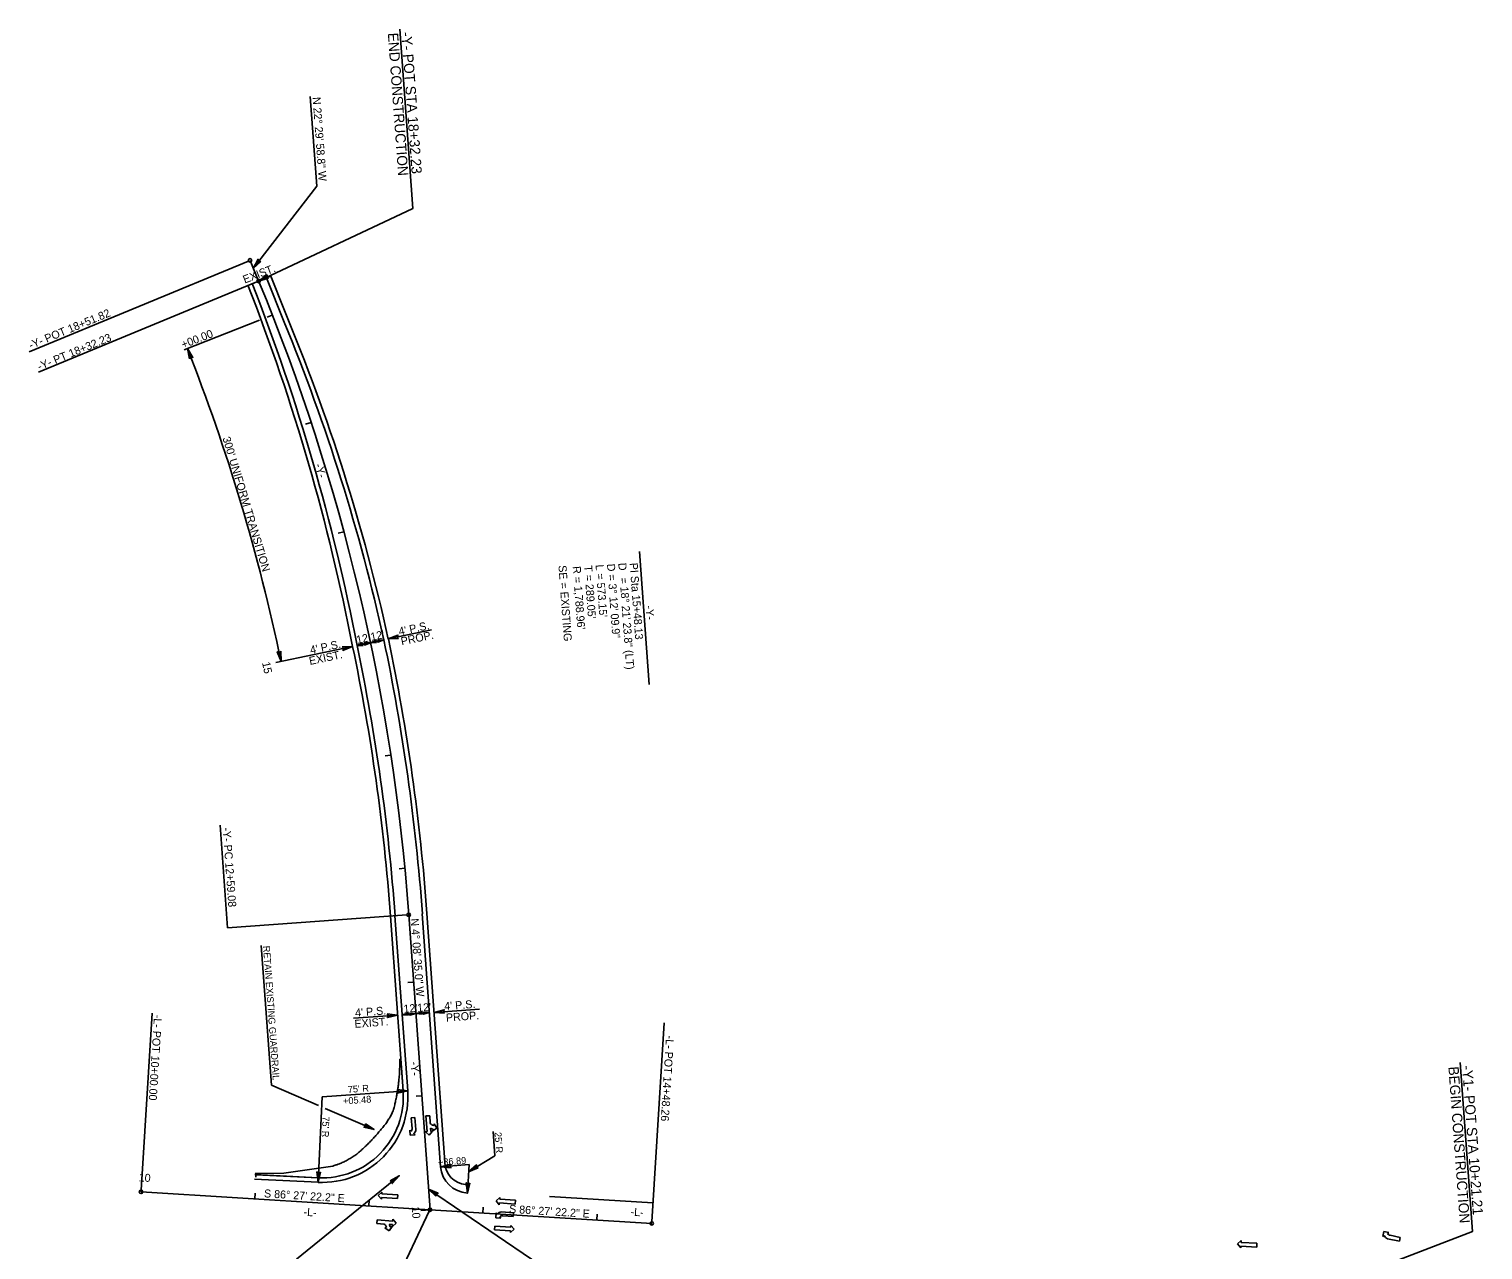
# Model space of a CAD drawing. Extents: x 2130900 to 2132500, y 642139 to 644213.
# Drawn here: x 2130900 to 2132174, y 643143 to 644213 of the extents above; entities that cross this region are included whole.
import ezdxf

# ---------------------------------------------------------------- set-up
doc = ezdxf.new("R2010")
doc.units = 0
for name, color, linetype in [('Prop Dimension', 7, 'Continuous'), ('Prop Dimension Text', 7, 'Continuous'), ('Prop DSN Text', 7, 'Continuous'), ('Prop EOT', 7, 'Continuous'), ('Prop Horizontal Alignment', 7, 'Continuous'), ('Prop Horizontal Alignment Curve and Spiral Data', 7, 'Continuous'), ('Prop Horizontal Alignment Direction Label', 7, 'Continuous'), ('Prop Horizontal Alignment Station Label', 7, 'Continuous'), ('Prop Horizontal Alignment Tick Label', 7, 'Continuous'), ('Prop Horizontal Alignment Tick Large', 7, 'Continuous'), ('Prop Horizontal Alignment Tick Small', 7, 'Continuous'), ('Prop Lane Lines', 7, 'Continuous'), ('Prop Paved Shoulder', 7, 'Continuous'), ('Prop Rem of Exist Asph Pvmt', 7, 'Continuous'), ('Prop Terminator CELL', 7, 'Continuous')]:
    doc.layers.add(name, color=color, linetype=linetype)

msp = doc.modelspace()

# ---------------------------------------------------------------- linework, layer by layer
at = {"layer": 'Prop Dimension'}
for p, q in [((2131102, 643957.9), (2131036, 643932)), ((2131199.2, 643675.3), (2131211, 643677.8)), ((2131214.9, 643678.6), (2131252.9, 643686.6)), ((2131116.5, 643657.9), (2131183.6, 643672)), ((2131187.5, 643672.8), (2131199.2, 643675.3)), ((2131184.4, 643346.3), (2131223.1, 643349.1)), ((2131227.1, 643349.4), (2131239, 643350.3)), ((2131239, 643350.3), (2131251, 643351.2)), ((2131255, 643351.4), (2131294.7, 643354.3)), ((2131231.9, 643282.8), (2131157.1, 643277.4))]:
    msp.add_line(p, q, dxfattribs=at)
msp.add_arc((2129448.5, 643307.7), 1709, 11.8592, 21.4674, dxfattribs=at)
at = {"layer": 'Prop Dimension Text'}
for p, q in [((2131103.7, 643410.1), (2131112.6, 643287.7)), ((2131112.6, 643287.7), (2131153.7, 643269.9)), ((2131159.7, 643267.2), (2131202.5, 643248.7)), ((2131399.3, 643095.3), (2131250.2, 643196.6))]:
    msp.add_line(p, q, dxfattribs=at)
for points in [[(2131224.9, 644213.1), (2131236.3, 644055.8), (2131101.3, 643992.3)], [(2132153.8, 643307.6), (2132164.7, 643159.4), (2132043.2, 643112.7)]]:
    msp.add_lwpolyline(points, dxfattribs=at)
at = {"layer": 'Prop DSN Text'}
for p, q in [((2131153.4, 643202.5), (2131157.1, 643277.4)), ((2131308.4, 643225.8), (2131306.9, 643247)), ((2131285.3, 643211.7), (2131308.4, 643225.8)), ((2131134.6, 643135.3), (2131224.5, 643208.3)), ((2131285.7, 643218), (2131260.8, 643216.2)), ((2131284.3, 643193), (2131285.7, 643218))]:
    msp.add_line(p, q, dxfattribs=at)
at = {"layer": 'Prop EOT'}
for p, q in [((2131101.3, 643992.3), (2131111.8, 643996.6)), ((2131123.7, 643956.1), (2131108.1, 643995.1)), ((2131095.7, 643989.9), (2131101.3, 643992.3)), ((2131231.9, 643282.8), (2131220.8, 643436)), ((2131260.8, 643216.2), (2131244.7, 643437.8)), ((2131097.7, 643205.3), (2131153.4, 643202.5))]:
    msp.add_line(p, q, dxfattribs=at)
for centre, radius, start, end in [((2129402.5, 643327.8), 1818.1, 10.9409, 21.3592), ((2129575, 643317.6), 1675.2, 12.4162, 22.4051), ((2129448.5, 643307.7), 1801, 4.1431, 11.8592), ((2129448.5, 643307.7), 1777, 4.1431, 11.8592), ((2131157.1, 643277.4), 75, 267.1687, 4.1431), ((2131285.7, 643218), 25, 184.1431, 266.6762)]:
    msp.add_arc(centre, radius, start, end, dxfattribs=at)
at = {"layer": 'Prop Horizontal Alignment'}
for p, q in [((2131101.3, 643992.3), (2131093.8, 644010.4)), ((2131251.5, 643178.5), (2131232.8, 643436.9)), ((2130998.3, 643194.2), (2131251.5, 643178.5)), ((2131251.5, 643178.5), (2131445.7, 643166.5))]:
    msp.add_line(p, q, dxfattribs=at)
msp.add_arc((2129448.5, 643307.7), 1789, 4.1431, 22.4997, dxfattribs=at)
at = {"layer": 'Prop Horizontal Alignment Curve and Spiral Data'}
msp.add_line((2131435.1, 643755.4), (2131443.5, 643638.7), dxfattribs=at)
at = {"layer": 'Prop Horizontal Alignment Direction Label'}
for p, q in [((2131152.3, 644075.3), (2131146.6, 644154.1)), ((2131096.5, 644003.3), (2131152.3, 644075.3))]:
    msp.add_line(p, q, dxfattribs=at)
at = {"layer": 'Prop Horizontal Alignment Station Label'}
for p, q in [((2131092.4, 644009.8), (2130900.2, 643930.2)), ((2131099.9, 643991.7), (2130908.5, 643912.4)), ((2131074.2, 643425.4), (2131067.7, 643515.4)), ((2131231.3, 643436.8), (2131074.2, 643425.4)), ((2130998.4, 643195.7), (2131008, 643350.8)), ((2131445.8, 643168), (2131456.6, 643342.2)), ((2131250.8, 643177.2), (2131211.1, 643093.2))]:
    msp.add_line(p, q, dxfattribs=at)
for centre in [(2131093.8, 644010.4), (2131101.3, 643992.3), (2131232.8, 643436.9), (2130998.3, 643194.2), (2131251.5, 643178.5), (2131251.5, 643178.5), (2131445.7, 643166.5)]:
    msp.add_circle(centre, 1.5, dxfattribs=at)
at = {"layer": 'Prop Horizontal Alignment Tick Large'}
for p, q in [((2131199.2, 643675.3), (2131191.4, 643673.7)), ((2130998.3, 643194.2), (2130998.8, 643202.2)), ((2131251.5, 643178.5), (2131243.5, 643177.9))]:
    msp.add_line(p, q, dxfattribs=at)
at = {"layer": 'Prop Horizontal Alignment Tick Small'}
for p, q in [((2131113.3, 643962.4), (2131108.7, 643960.5)), ((2131147.3, 643868.3), (2131142.5, 643866.8)), ((2131176, 643772.5), (2131171.1, 643771.2)), ((2131217, 643576.9), (2131212.1, 643576.2)), ((2131229.3, 643477.7), (2131224.4, 643477.2)), ((2131237, 643378), (2131232, 643377.6)), ((2131244.2, 643278.2), (2131239.3, 643277.9)), ((2131098.1, 643188), (2131098.4, 643193)), ((2131197.9, 643181.8), (2131198.2, 643186.8)), ((2131297.7, 643175.6), (2131298.1, 643180.6)), ((2131397.6, 643169.5), (2131397.9, 643174.5))]:
    msp.add_line(p, q, dxfattribs=at)
at = {"layer": 'Prop Lane Lines'}
msp.add_line((2131356.2, 643190.1), (2131446.8, 643184.4), dxfattribs=at)
at = {"layer": 'Prop Paved Shoulder'}
for p, q in [((2131123.9, 643966.5), (2131111.9, 643996.6)), ((2131227.9, 643282.6), (2131216.8, 643435.8)), ((2131264.8, 643216.5), (2131248.7, 643438.1)), ((2131097.9, 643209.3), (2131153.6, 643206.5))]:
    msp.add_line(p, q, dxfattribs=at)
for centre, radius, start, end in [((2129402.5, 643327.8), 1814.1, 10.9409, 21.3592), ((2129574.8, 643318.3), 1679.2, 12.3892, 22.706), ((2129448.5, 643307.7), 1805, 4.1431, 11.8598), ((2129448.5, 643307.7), 1773, 4.1431, 11.8592), ((2131157.1, 643277.4), 71, 267.1687, 4.1431), ((2131284.6, 643220.7), 20.3, 192.2078, 274.7409)]:
    msp.add_arc(centre, radius, start, end, dxfattribs=at)
at = {"layer": 'Prop Rem of Exist Asph Pvmt'}
for p, q in [((2131225.9, 643310.3), (2131225, 643310.3)), ((2131227.9, 643282.6), (2131225.9, 643310.3)), ((2131098.8, 643210.8), (2131099, 643207)), ((2131123.5, 643210.5), (2131098.8, 643210.2)), ((2131098.8, 643210.2), (2131098.9, 643209.2)), ((2131098.9, 643209.2), (2131153.6, 643206.5))]:
    msp.add_line(p, q, dxfattribs=at)
msp.add_lwpolyline([(2131166.2, 643216.7), (2131148, 643213.9), (2131123.5, 643210.5)], dxfattribs=at)
msp.add_arc((2131157.1, 643277.4), 71, 267.1687, 4.1431, dxfattribs=at)
msp.add_open_spline([(2131225, 643310.3), (2131225, 643304.8), (2131224.8, 643299.4), (2131224.4, 643293.9), (2131224, 643289.9), (2131223.5, 643286), (2131222.8, 643282), (2131222.2, 643278), (2131221.4, 643274), (2131220.5, 643270.1), (2131220.1, 643268.1), (2131219.4, 643266.2), (2131218.7, 643264.3), (2131218, 643262.5), (2131217.1, 643260.7), (2131216.1, 643259), (2131213.8, 643255.5), (2131211.5, 643252.2), (2131208.8, 643249.1), (2131206.1, 643245.9), (2131203.4, 643242.7), (2131200.5, 643239.7), (2131197.7, 643236.7), (2131194.8, 643233.9), (2131191.8, 643231.1), (2131188.9, 643228.5), (2131185.8, 643226.1), (2131182.4, 643224), (2131179, 643221.9), (2131175.5, 643220.1), (2131171.8, 643218.7), (2131170, 643218), (2131168.1, 643217.4), (2131166.2, 643216.7)], degree=3, dxfattribs=at)
at = {"layer": 'Prop Terminator CELL'}
for p, q in [((2131238.2, 643259.3), (2131234.9, 643259)), ((2131239.1, 643248.8), (2131238.2, 643259.3)), ((2131251.2, 643260.9), (2131247.9, 643260.7)), ((2131247.9, 643260.7), (2131248.9, 643246.9)), ((2131251.7, 643254.5), (2131251.2, 643260.9)), ((2131234.8, 643247.3), (2131233.7, 643248.2)), ((2131233.7, 643248.2), (2131234.1, 643243.8)), ((2131234.1, 643243.8), (2131238.5, 643244.1)), ((2131234.8, 643247.3), (2131234.8, 643247.3)), ((2131239.1, 643248.7), (2131239.1, 643248.8)), ((2131248.9, 643246.9), (2131247.4, 643246.8)), ((2131247.4, 643246.8), (2131250.7, 643243.9)), ((2131250.7, 643243.9), (2131253.7, 643247.2)), ((2131252.2, 643247.1), (2131252, 643250)), ((2131253.7, 643247.2), (2131252.2, 643247.1)), ((2131253.8, 643247.5), (2131257.5, 643250)), ((2131254.1, 643249), (2131253.8, 643247.5)), ((2131255.1, 643253.7), (2131254.8, 643252.3)), ((2131257.5, 643250), (2131255.1, 643253.7)), ((2131206.1, 643191), (2131209.4, 643193.9)), ((2131209.4, 643193.9), (2131209.3, 643192.4)), ((2131209.1, 643187.7), (2131206.1, 643191)), ((2131223.1, 643188.3), (2131209.1, 643189.1)), ((2131209.1, 643189.1), (2131209.1, 643187.7)), ((2131209.3, 643192.4), (2131223.3, 643191.6)), ((2131223.3, 643191.6), (2131223.1, 643188.3)), ((2131309.3, 643186.2), (2131312.6, 643189.1)), ((2131312.2, 643182.9), (2131309.3, 643186.2)), ((2131312.3, 643184.4), (2131312.2, 643182.9)), ((2131326.2, 643183.5), (2131312.3, 643184.4)), ((2131312.6, 643189.1), (2131312.5, 643187.7)), ((2131312.5, 643187.7), (2131326.4, 643186.8)), ((2131326.4, 643186.8), (2131326.2, 643183.5)), ((2131204.8, 643166.4), (2131205.1, 643169.7)), ((2131205.1, 643169.7), (2131218.8, 643168.6)), ((2131218.8, 643168.6), (2131219, 643170.1)), ((2131219, 643170.1), (2131221.8, 643166.8)), ((2131309.5, 643175.9), (2131309.2, 643171.4)), ((2131309.2, 643171.4), (2131313.6, 643171.2)), ((2131310.6, 643174.6), (2131309.5, 643175.9)), ((2131313.6, 643171.2), (2131312.7, 643172.2)), ((2131324.6, 643175.9), (2131314.1, 643176.6)), ((2131315.2, 643173.2), (2131324.4, 643172.6)), ((2131324.4, 643172.6), (2131324.6, 643175.9)), ((2131211.3, 643165.9), (2131204.8, 643166.4)), ((2131212, 643162.5), (2131213.4, 643162.8)), ((2131215.7, 643160), (2131212, 643162.5)), ((2131218.2, 643163.7), (2131215.7, 643160)), ((2131218.6, 643165.4), (2131215.8, 643165.6)), ((2131216.7, 643163.4), (2131218.2, 643163.7)), ((2131221.8, 643166.8), (2131218.5, 643163.9)), ((2131218.5, 643163.9), (2131218.6, 643165.4)), ((2131308.1, 643160.8), (2131308.3, 643164.1)), ((2131322.1, 643159.9), (2131308.1, 643160.8)), ((2131308.3, 643164.1), (2131322.3, 643163.2)), ((2131325.3, 643161.4), (2131322, 643158.5)), ((2131322, 643158.5), (2131322.1, 643159.9)), ((2131322.3, 643163.2), (2131322.3, 643164.7)), ((2131322.3, 643164.7), (2131325.3, 643161.4)), ((2132086.2, 643155.1), (2132087.1, 643159.4)), ((2132087.5, 643155.9), (2132086.2, 643155.1)), ((2132087.1, 643159.4), (2132091.5, 643158.5)), ((2132091.5, 643158.5), (2132090.2, 643157.7)), ((2132092.5, 643156.1), (2132101.4, 643154.2)), ((2131958.8, 643148.5), (2131962.1, 643151.4)), ((2131961.7, 643145.2), (2131958.8, 643148.5)), ((2131961.8, 643146.6), (2131961.7, 643145.2)), ((2131975.7, 643145.8), (2131961.8, 643146.6)), ((2131962.1, 643151.4), (2131962, 643149.9)), ((2131962, 643149.9), (2131975.9, 643149.1)), ((2131975.9, 643149.1), (2131975.7, 643145.8)), ((2132100.8, 643151), (2132090.4, 643153.1)), ((2132101.4, 643154.2), (2132100.8, 643151))]:
    msp.add_line(p, q, dxfattribs=at)
for points in [[(2131103.3, 644009.4), (2131096.5, 644003.3), (2131100.8, 644011.4), (2131101.4, 644009.5)], [(2131110.1, 643994.7), (2131101.3, 643992.3), (2131108.8, 643997.6), (2131108.4, 643995.6)], [(2131040.8, 643924.2), (2131038.9, 643933.1), (2131043.7, 643925.3), (2131041.8, 643925.8)], [(2131204.7, 643675.5), (2131199.2, 643675.3), (2131204.4, 643677.4), (2131203.9, 643676.3)], [(2131205.5, 643677.6), (2131211, 643677.8), (2131205.9, 643675.7), (2131206.3, 643676.8)], [(2131224, 643678.9), (2131214.9, 643678.6), (2131223.4, 643682), (2131222.6, 643680.2)], [(2131120.7, 643668), (2131121, 643658.9), (2131117.6, 643667.4), (2131119.4, 643666.6)], [(2131174.5, 643671.7), (2131183.6, 643672), (2131175.1, 643668.6), (2131175.9, 643670.4)], [(2131193, 643673), (2131187.5, 643672.8), (2131192.6, 643674.9), (2131192.1, 643673.8)], [(2131193.8, 643675.1), (2131199.2, 643675.3), (2131194.1, 643673.2), (2131194.6, 643674.3)], [(2131214, 643350), (2131223.1, 643349.1), (2131214.2, 643346.9), (2131215.2, 643348.6)], [(2131232.5, 643348.9), (2131227.1, 643349.4), (2131232.4, 643350.8), (2131231.8, 643349.8)], [(2131233.6, 643350.8), (2131239, 643350.3), (2131233.7, 643348.9), (2131234.3, 643349.9)], [(2131244.5, 643349.8), (2131239, 643350.3), (2131244.4, 643351.6), (2131243.8, 643350.6)], [(2131245.5, 643351.7), (2131251, 643351.2), (2131245.6, 643349.8), (2131246.3, 643350.8)], [(2131264.1, 643350.6), (2131255, 643351.4), (2131263.9, 643353.7), (2131262.9, 643352)], [(2131222.8, 643283.7), (2131231.9, 643282.8), (2131223, 643280.6), (2131224, 643282.3)], [(2131194.9, 643253.7), (2131202.5, 643248.7), (2131193.6, 643250.8), (2131195.3, 643251.8)], [(2131269.9, 643215.3), (2131260.8, 643216.2), (2131269.7, 643218.4), (2131268.7, 643216.7)], [(2131155.4, 643211.4), (2131153.4, 643202.5), (2131152.2, 643211.6), (2131153.8, 643210.4)], [(2131216.5, 643203.8), (2131224.5, 643208.3), (2131218.4, 643201.4), (2131218.3, 643203.3)], [(2131293.8, 643215.1), (2131285.3, 643211.7), (2131292.2, 643217.8), (2131292.1, 643215.8)], [(2131256.7, 643190.3), (2131250.2, 643196.6), (2131258.5, 643192.9), (2131256.7, 643192.2)], [(2131286.3, 643201.9), (2131284.3, 643193), (2131283.2, 643202.1), (2131284.7, 643200.9)]]:
    msp.add_lwpolyline(points, close=True, dxfattribs=at)
for points in [[(2131234.9, 643259), (2131235.7, 643249.8), (2131235.7, 643249.8)], [(2131238.5, 643244.1), (2131237.3, 643245.1), (2131237.3, 643245.2), (2131237.3, 643245.1)]]:
    msp.add_lwpolyline(points, dxfattribs=at)
for centre, radius, start, end in [((2131232.5, 643249.5), 3.26, 315.2154, 4.8735), ((2131233.9, 643249.1), 5.22, 310.8858, 356.1975), ((2131254, 643255.3), 2.52, 198.6769, 234.9889), ((2131254.7, 643253.4), 4.43, 231.5926, 262.4712), ((2131255.4, 643256.7), 4.43, 231.4988, 262.3524), ((2131314.5, 643171.4), 5.22, 95.0317, 140.3434), ((2131315, 643170), 3.26, 86.3556, 136.0138), ((2131210.5, 643163.5), 2.52, 34.8302, 71.1422), ((2131209, 643162.2), 4.43, 7.4667, 38.3203), ((2131212.3, 643162.8), 4.43, 7.3479, 38.2265), ((2132092.2, 643158), 5.25, 204.3747, 249.6864), ((2132093.1, 643159.3), 3.27, 208.7043, 258.3624)]:
    msp.add_arc(centre, radius, start, end, dxfattribs=at)

# ---------------------------------------------------------------- texts
at = {"layer": 'Prop Dimension Text'}
for s, height, rotation, p in [('END CONSTRUCTION', 9, 274.1585, (2131214.5, 644209.5)), ('-Y- POT STA 18+32.23', 9, 274.1585, (2131226.4, 644210.3)), ('EXIST.', 7, 21.1953, (2131089.2, 643990)), ('+00.00', 7, 21.2777, (2131035.2, 643933)), ("300' UNIFORM TRANSITION", 7, 286.7112, (2131069.6, 643854.7)), ("4' P.S.", 7, 11.8592, (2131224.7, 643681.7)), ("4' P.S.", 7, 11.8592, (2131147.1, 643665.4)), ("12'", 7, 11.8592, (2131187.7, 643674.3)), ("12'", 7, 11.8592, (2131200.1, 643676.9)), ('PROP.', 7, 11.8592, (2131226.7, 643673)), ('EXIST.', 7, 11.8592, (2131146.3, 643655.8)), ('RETAIN EXISTING GUARDRAIL', 6, 274.1585, (2131105.2, 643409.6)), ("12'", 7, 4.3863, (2131228.5, 643351)), ("12'", 7, 4.3863, (2131240.5, 643351.8)), ("4' P.S.", 7, 4.3863, (2131264.2, 643353.3)), ('EXIST.', 7, 4.3863, (2131185.6, 643337.8)), ("4' P.S.", 7, 4.3863, (2131186.1, 643347.6)), ('PROP.', 7, 4.3863, (2131265.7, 643343.3)), ('BEGIN CONSTRUCTION', 9, 274.1585, (2132143.6, 643303.7)), ('-Y1- POT STA 10+21.21', 9, 274.1585, (2132155.6, 643304.6)), ("75' R", 6, 4.1431, (2131179.7, 643280.8)), ('+05.48', 6, 4.1431, (2131175.5, 643270.7)), ("75' R", 6, 268.4191, (2131157.3, 643260.4)), ("25' R", 6, 274.1431, (2131308, 643246.3)), ('+36.89', 6, 4.1431, (2131258.7, 643217))]:
    msp.add_text(s, height=height, rotation=rotation, dxfattribs=at).set_placement(p)
at = {"layer": 'Prop Horizontal Alignment Curve and Spiral Data'}
for s, p in [('SE = EXISTING', (2131364, 643743)), ("R = 1,788.96'", (2131376.5, 643742.2)), ("T = 289.05'", (2131386.5, 643742.9)), ("L = 573.15'", (2131396.5, 643743.6)), ('D = 3%%d 12\' 09.9"', (2131406.5, 643744.3)), ('D', (2131416.4, 643745.1)), ('PI Sta 15+48.13', (2131426.4, 643745.1)), ('= 18%%d 21\' 23.8" (LT)', (2131417.6, 643732.3))]:
    msp.add_text(s, height=7, rotation=274.1431, dxfattribs=at).set_placement(p)
at = {"layer": 'Prop Horizontal Alignment Direction Label'}
for s, rotation, p in [('N 22%%d 29\' 58.8" W', 274.1585, (2131148.6, 644153.3)), ('-Y-', 287.1037, (2131150.4, 643831.1)), ('-Y-', 274.1431, (2131440.2, 643707.6)), ('N 4%%d 08\' 35.0" W', 274.1431, (2131234.5, 643433.5)), ('-Y-', 274.1431, (2131234.4, 643308.2)), ('S 86%%d 27\' 22.2" E', 356.4562, (2131105.9, 643189.4)), ('-L-', 356.4562, (2131140.5, 643173.2)), ('S 86%%d 27\' 22.2" E', 356.4562, (2131320.6, 643175.8)), ('-L-', 356.4562, (2131427, 643173.3))]:
    msp.add_text(s, height=7, rotation=rotation, dxfattribs=at).set_placement(p)
at = {"layer": 'Prop Horizontal Alignment Station Label'}
for s, rotation, p in [('-Y- POT 18+51.82', 22.4997, (2130901.7, 643932.5)), ('-Y- PT 18+32.23', 22.4997, (2130909.3, 643913.8)), ('-Y- PC 12+59.08', 274.1431, (2131069.8, 643513.2)), ('-L- POT 10+00.00', 266.4562, (2131009.7, 643349.5)), ('-L- POT 14+48.26', 266.4562, (2131458.3, 643331.2))]:
    msp.add_text(s, height=7, rotation=rotation, dxfattribs=at).set_placement(p)
at = {"layer": 'Prop Horizontal Alignment Tick Label'}
for s, rotation, p in [('15', 281.8592, (2131104.3, 643657.9)), ('10', 356.4562, (2130996.1, 643203.4)), ('10', 274.1431, (2131235.4, 643181))]:
    msp.add_text(s, height=7, rotation=rotation, dxfattribs=at).set_placement(p)

doc.saveas('drawing.dxf')
